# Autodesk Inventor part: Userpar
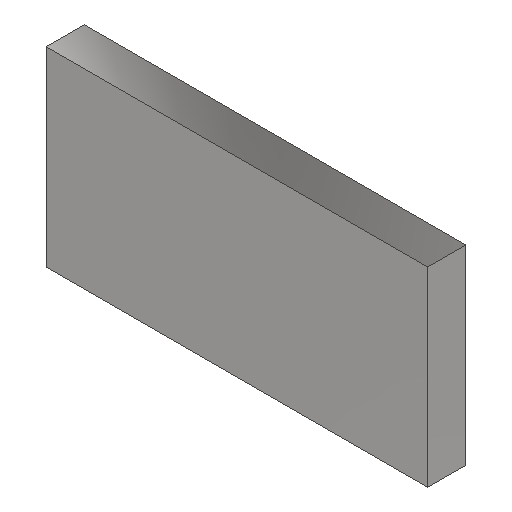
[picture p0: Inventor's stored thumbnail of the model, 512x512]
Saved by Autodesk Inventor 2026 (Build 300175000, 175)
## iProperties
Created: 2022-10
Part Number: Userpar
Material: Steel, Mild
Document SubType Name: Modeling
Designer: Lars Bertram Pedersen
Density: 7.85 g/cm^3
Appearance: Semi-Polished
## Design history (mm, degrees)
sketch "Sketch1"
  geometry: L1 (-25, -12.5)-(25, -12.5); L2 (25, -12.5)-(25, 12.5); L3 (25, 12.5)-(-25, 12.5); L4 (-25, 12.5)-(-25, -12.5); L5 (-25, -12.5)-(25, 12.5); L6 (25, -12.5)-(-25, 12.5); 1 further point
  constraints: 12 end point, 2 midpoint, 2 parallel, 1 horizontal, 1 perpendicular
  dimensions: "d0" = 50 distance of L2.end L3.end (= Længde); "d1" = 25 distance of L3.end L1.start (= Bredde)
extrude "Extrusion1" new body sketch "Sketch1" distance "d2" = 5 (= Dybde); taper "d3" = 0 deg
body "Solid1"
other parameters: "Længde" = 50 [user parameter; used in 1 equation term], "Bredde" = 25 [user parameter; used in 1 equation term], "Dybde" = 5 [user parameter; used in 1 equation term]
